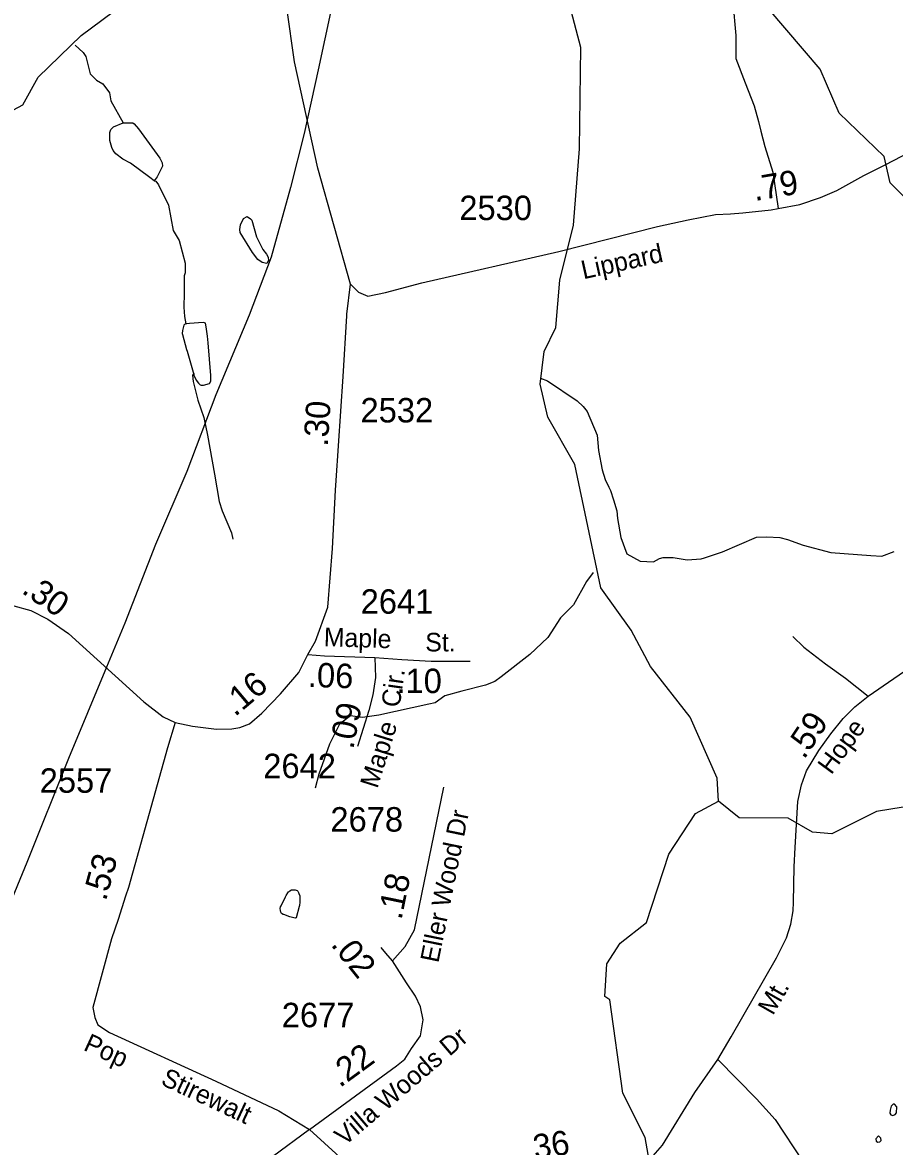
# Model space of a CAD drawing. Extents: x 1473865 to 1648260, y 639067 to 773536.
# Drawn here: x 1556744 to 1561206, y 667690 to 673439 of the extents above; entities that cross this region are included whole.
import ezdxf

# ---------------------------------------------------------------- set-up
doc = ezdxf.new("R2010")
doc.units = 0
for name, color, linetype in [('Exist Hydrographic Creek Single Shore', 7, 'Continuous'), ('Exist Hydrographic Misc Water Feature', 7, 'Continuous'), ('Exist Road Non-System Type 51', 7, 'Continuous'), ('Exist Road Secondary Mileage Hundredths English Label', 7, 'Continuous'), ('Exist Road Secondary Type 51 Attributed', 7, 'Continuous'), ('Exist Road Secondary Type 51 Label', 7, 'Continuous'), ('Exist Road Secondary Type 51 Number Label', 7, 'Continuous'), ('Exist Utilities Electrical Transmission Line', 7, 'Continuous')]:
    doc.layers.add(name, color=color, linetype=linetype)

msp = doc.modelspace()

# ---------------------------------------------------------------- linework, layer by layer
at = {"layer": 'Exist Hydrographic Creek Single Shore'}
for points in [[(1560304.5, 669456), (1560297.4, 669574.3), (1560160.4, 669885.6), (1559956.5, 670145.7), (1559858.5, 670331.6), (1559703.5, 670548.1), (1559570.5, 671177.7), (1559432.5, 671420.1), (1559393.4, 671588.3), (1559412.5, 671755.3), (1559472.5, 671878.8), (1559492.5, 672121.3), (1559563.5, 672402.2), (1559594.5, 672792.2), (1559601.4, 673310.7), (1559351.6, 674255.1), (1559302.9, 674358.3), (1559271.4, 674498.8)], [(1555070.4, 671875.8), (1555263.5, 671947.4), (1555572.5, 671960.9), (1555791.5, 672114), (1555983.4, 672146.2), (1556110.4, 672261.8), (1556286.5, 672333.7), (1556363.5, 672466.8), (1556399.4, 672646.6), (1556526.5, 672811.5), (1556578.5, 672928.5), (1556746.5, 673017.1), (1556823.5, 673159.9), (1557043.4, 673372.1), (1557481.5, 673698.1), (1557672.5, 673648.3), (1557798.5, 673678.6), (1557883.5, 673834.4), (1557865.7, 674112.6), (1557939.2, 674210.1), (1558074.5, 674332.8), (1558259.5, 674430.8)], [(1561675.9, 665105.2), (1561484.1, 665152.9), (1561127.3, 665283.8), (1560879.4, 665387.3), (1560665.3, 665624.6), (1560502.3, 665870.9), (1560370.4, 665978.5), (1560225.4, 666290), (1560086.4, 666516.1), (1560050.4, 666900.8), (1560011.4, 667052.6), (1559962.4, 667135.7), (1559931.4, 667326.6), (1559960.4, 667562.4), (1559929.4, 667737), (1559815.4, 667962.5), (1559748.5, 668439.9), (1559723.4, 668456.7), (1559733.4, 668623.9), (1559802.4, 668730.8), (1559937.4, 668836.5), (1560050.4, 669185.4), (1560186.5, 669392.7), (1560304.5, 669456)]]:
    msp.add_lwpolyline(points, dxfattribs=at)
at = {"layer": 'Exist Hydrographic Misc Water Feature'}
msp.add_line((1557617.4, 671650.6), (1557619.1, 671639.2), dxfattribs=at)
for points in [[(1561348.5, 672451.5), (1561183.5, 672618.9), (1561152.5, 672754.1), (1560922.5, 672975.5), (1560825.5, 673200.6), (1560563.4, 673504.6), (1560402.5, 673914.8), (1560221.5, 674102.4), (1560214.5, 674168.1), (1560140.5, 674268.1), (1559975.5, 674389.6), (1559861.5, 674549.4), (1559748.5, 674768.4), (1559732.5, 674840.9), (1559530.5, 675271.7), (1559472.5, 675322.1), (1559380.5, 675330.5)], [(1557013.2, 673322.3), (1557054.1, 673285.3), (1557067.8, 673265.1), (1557090.9, 673176.9), (1557122.6, 673144.5), (1557155.3, 673124.6), (1557189.8, 673079.7), (1557195.4, 673037.6), (1557259.3, 672925.3)], [(1557416.9, 672628.3), (1557395.1, 672645.3), (1557295.8, 672718.5), (1557258.1, 672738.9), (1557222.4, 672767.3), (1557208.6, 672783.5), (1557200.7, 672799.6), (1557191.2, 672835.7), (1557191.6, 672875.7), (1557195.8, 672891.6), (1557209.9, 672905.5), (1557259.3, 672925.3)], [(1557259.3, 672925.3), (1557308.1, 672926.3), (1557316.1, 672920.2), (1557337.9, 672894), (1557446.2, 672744.7), (1557457.9, 672720.6), (1557459.8, 672704.5), (1557433.1, 672648.9), (1557416.9, 672628.3)], [(1557416.9, 672628.3), (1557426.9, 672626.9), (1557440.7, 672608.8), (1557491.6, 672504.1), (1557515.7, 672374.2), (1557545.6, 672323.5), (1557576.3, 672207.1), (1557575.8, 672159.1), (1557571.6, 672143.2), (1557570.6, 672055.2), (1557569.9, 671983.2), (1557573.3, 671935.2), (1557580.4, 671897.3)], [(1557892.7, 672445.9), (1557911, 672435.2), (1557916.9, 672427.2), (1557942, 672342.9), (1557973.2, 672278.5), (1557993, 672254.3), (1558000.8, 672238.2), (1558002.6, 672222.2), (1557994.4, 672206.3), (1557970.6, 672210.6), (1557948.7, 672226.8), (1557921, 672263.2), (1557858.2, 672363.9), (1557856.3, 672379.9), (1557858.6, 672403.9), (1557875, 672435.7), (1557892.7, 672445.9)], [(1557580.4, 671897.3), (1557572.1, 671893.9), (1557568.9, 671889.9), (1557567.1, 671884.2), (1557565.4, 671877.6), (1557562.7, 671862.9), (1557561.7, 671848.1), (1557562.5, 671843.2), (1557583.6, 671765.9), (1557586, 671757.6), (1557617.4, 671650.6)], [(1557619.1, 671639.2), (1557632.5, 671608.6), (1557644.7, 671594.4), (1557652.8, 671585.3), (1557657.6, 671584.4), (1557661.7, 671584.4), (1557670.8, 671584.3), (1557700.4, 671592.1), (1557708, 671604.3), (1557706.8, 671633.8), (1557694, 671800.5), (1557690.4, 671835), (1557683.6, 671882.6), (1557680.5, 671900.7), (1557674.8, 671902.4), (1557668.2, 671904.2), (1557599.3, 671899.3), (1557585.4, 671897.9), (1557580.4, 671897.3)], [(1557619.1, 671639.2), (1557614, 671634.7), (1557617.7, 671602.6), (1557640.6, 671506.3), (1557671.6, 671418), (1557691.3, 671328.4), (1557726.4, 671129.3), (1557750.9, 670989), (1557766.3, 670940.8), (1557813.2, 670828.2), (1557820.8, 670796.2)], [(1557617.4, 671650.6), (1557622.3, 671640.7), (1557619.1, 671639.2)], [(1559393.5, 671620), (1559430.3, 671605.5), (1559581.3, 671503.7), (1559613, 671475.3), (1559632.7, 671449.1), (1559683.9, 671327.4), (1559690.5, 671250.4), (1559709.4, 671150.2), (1559724.9, 671102), (1559744.5, 671061.8), (1559752.3, 671045.7), (1559767.7, 670997.5), (1559785.2, 670941.3), (1559788.8, 670901.2), (1559805.7, 670805), (1559836.7, 670720.6), (1559904.3, 670683.9), (1559972.4, 670681.1), (1560002.5, 670696.8), (1560022.6, 670702.5), (1560072.6, 670701.9), (1560144.5, 670691.1), (1560216.6, 670696.2), (1560232.7, 670700), (1560325.1, 670731), (1560500, 670807), (1560552, 670808.4), (1560618, 670805.6), (1560657.9, 670795.1), (1560737.5, 670766.2), (1560879.2, 670728.5), (1561085.1, 670712.1), (1561141.1, 670709.5), (1561203.4, 670732.7)], [(1559664.1, 670626.5), (1559629.1, 670579.1), (1559563.7, 670459.8), (1559497, 670394.6), (1559431.9, 670293.7), (1559338.9, 670206.4), (1559193.5, 670092.1), (1559161.3, 670068.5), (1559113, 670049.1), (1558992.6, 670018.4), (1558904.4, 669995.5), (1558856, 669960), (1558823.8, 669952.4), (1558567.1, 669895.4), (1558483, 669884.3), (1558423, 669893.1), (1558366.5, 669849.7), (1558315.4, 669748.3), (1558259.7, 669594.9), (1558240.8, 669523.1)], [(1563318.4, 667461.8), (1563195.4, 667638.2), (1563174.5, 667871.7), (1563126.4, 667997.4), (1562839.4, 668328.2), (1562832.4, 668426.8), (1562750.4, 668546.6), (1562822.4, 668896.4), (1562789.5, 668929.9), (1562580.4, 668898), (1562406.4, 668944.2), (1562182.4, 669070.1), (1562092.4, 669180.3), (1562028.4, 669349), (1561806.5, 669527.5), (1561673.5, 669579.4), (1561514.5, 669562.9), (1561312.4, 669435.6), (1561112.5, 669403.5), (1560885.5, 669290), (1560785.4, 669298.6), (1560661.5, 669370), (1560411.4, 669371.8), (1560304.5, 669456)], [(1558143.5, 668859), (1558138.7, 668857.9), (1558112, 668865.4), (1558081.5, 668875.9), (1558078.3, 668877.3), (1558069.8, 668881.5), (1558066.9, 668885.2), (1558065, 668888.7), (1558063.6, 668897.1), (1558062.9, 668907.7), (1558064.8, 668915.1), (1558066.8, 668920.3), (1558089, 668967.4), (1558093.1, 668974.5), (1558101.6, 668988.1), (1558105.4, 668992.1), (1558108.2, 668994.6), (1558112.2, 668997.7), (1558119.8, 669002), (1558126.4, 669002.7), (1558139.3, 669002.3), (1558144.4, 669001.3), (1558149.9, 668999.2), (1558152.7, 668996.1), (1558155.8, 668990), (1558158.6, 668983.7), (1558163.1, 668972.9), (1558163.7, 668958.9), (1558163.6, 668949.4), (1558163.2, 668940), (1558160.7, 668922.2), (1558159.8, 668917.9), (1558143.5, 668859)], [(1561183.5, 667876.4), (1561181.6, 667860.7), (1561187.5, 667852.7), (1561197.5, 667848.5), (1561209.6, 667854.4), (1561215.6, 667862.3), (1561218, 667892.3), (1561206.1, 667906.5), (1561198.1, 667906.6), (1561187.9, 667896.7), (1561183.5, 667876.4)], [(1561122.8, 667745.3), (1561110.1, 667729.6), (1561112, 667717.6), (1561119.8, 667711.5), (1561129.9, 667713.4), (1561138, 667721.2), (1561136.1, 667733.2), (1561122.8, 667745.3)]]:
    msp.add_lwpolyline(points, dxfattribs=at)
at = {"layer": 'Exist Road Non-System Type 51'}
for points in [[(1560378.4, 673541.8), (1560393, 673371.8), (1560394.1, 673254), (1560441.1, 673130.2), (1560488, 673013), (1560509.1, 672931.7)], [(1560509.1, 672931.7), (1560521.9, 672882.5), (1560542.2, 672804.2), (1560582.7, 672673.8), (1560610.8, 672487.9)], [(1560684.7, 670297.7), (1560742.2, 670243.1), (1560851.6, 670158.1), (1560954.9, 670085.2), (1561070.3, 669992.8)]]:
    msp.add_lwpolyline(points, dxfattribs=at)
at = {"layer": 'Exist Road Secondary Type 51 Attributed'}
for points in [[(1558421.7, 672101.1), (1558254.7, 672692.9), (1558135.5, 673238), (1558056.4, 673791), (1558049.7, 673925), (1558010.9, 674035.3), (1557970.5, 674132.9), (1557939.2, 674210.1), (1557902.5, 674316.9), (1557879.9, 674400.7), (1557859.9, 674633), (1557849.3, 674791.1), (1557837, 674971.2), (1557827.1, 675213.4), (1557809, 675437.6), (1557797.3, 675679.8), (1557760, 676212.4), (1557744, 676668.5), (1557744.5, 677160.4), (1557747.3, 677276.8), (1557748.8, 677432.8), (1557735.9, 677902.4)], [(1558421.7, 672101.1), (1558463.2, 672058.8), (1558511, 672038.2), (1558601.3, 672057.4), (1558787.8, 672107.7), (1559487.5, 672267.2), (1559992.9, 672394.7), (1560149.3, 672429.1), (1560289.7, 672455.9), (1560366, 672460.7), (1560429.7, 672464.7), (1560574, 672481.2), (1560610.8, 672487.9), (1560720.4, 672507.9), (1560826.7, 672542.9), (1560911.1, 672580.2), (1561047.9, 672656.9), (1561158.4, 672709.9), (1561413.7, 672843.6)], [(1558204.7, 670206.7), (1558243.3, 670274.4), (1558306.8, 670447.8), (1558329.5, 670747.7), (1558346.2, 671047.5), (1558349.5, 671096.8), (1558385.3, 671627.4), (1558403.6, 671937.9), (1558404.2, 671947.3), (1558421.7, 672101.1)], [(1556144.6, 670572.3), (1556436.5, 670513.2), (1556700, 670454.6), (1556786, 670431.9), (1556873.5, 670387.1), (1556978.9, 670314.1), (1557364, 669964.4), (1557463.3, 669887.3), (1557525.2, 669858.9)], [(1560301.6, 668135.2), (1560370.6, 668250.7), (1560602.3, 668654.6), (1560653.2, 668758.2), (1560675.8, 668828), (1560686.4, 668896), (1560688.9, 668940), (1560692.3, 669120), (1560697.3, 669219.9), (1560711.3, 669454), (1560730, 669539.8), (1560754.7, 669611.6), (1560817.6, 669714.9), (1560880.5, 669800.5), (1560943.2, 669879.9), (1561001.8, 669939.3), (1561070.3, 669992.8), (1561333.9, 670174.3), (1561466.7, 670259.1), (1561822.9, 670488), (1561923.6, 670559)], [(1557525.2, 669858.9), (1557613, 669840.1), (1557737, 669824.8), (1557815, 669826.2), (1557855.2, 669833.8), (1557905.4, 669851.4), (1557967.7, 669906.8), (1558064.8, 670005.9), (1558157.8, 670115), (1558204.7, 670206.7)], [(1558204.7, 670206.7), (1558288.6, 670199.8), (1558546.6, 670191.4)], [(1558546.6, 670191.4), (1558549.7, 670089.3), (1558536.9, 669999.5), (1558516.3, 669919.7), (1558458.7, 669736.1)], [(1558546.6, 670191.4), (1558684.6, 670180.2), (1558834.7, 670172.8), (1559034.8, 670173)], [(1557525.2, 669858.9), (1557485.9, 669729.2), (1557285.6, 669014.9), (1557271.8, 668970.9), (1557234.1, 668851.3), (1557199.3, 668751.5), (1557103.9, 668400.3), (1557113.5, 668350.3), (1557129.1, 668312.1), (1557189, 668273.5), (1557733, 668024.4), (1558055.7, 667873.4), (1558212.3, 667777.2)], [(1558636.6, 668639.8), (1558701.4, 668712.9), (1558750.4, 668798), (1558899.1, 669527.8)], [(1558636.6, 668639.8), (1558603.4, 668678.3), (1558578.9, 668707.1)], [(1558212.3, 667777.2), (1558657.6, 668102.6), (1558700, 668136.5), (1558733.9, 668191.7), (1558780.5, 668255.3), (1558793.6, 668337.8), (1558780.5, 668403.8), (1558755.1, 668458.9), (1558708.4, 668526.8), (1558636.6, 668639.8)], [(1558741.6, 667295.5), (1558798.1, 667349), (1558880.5, 667398.1), (1559069.3, 667492.4), (1559199.7, 667531.4), (1559350.1, 667553.9), (1559476.2, 667556.8), (1559598.2, 667553.5), (1559716.3, 667558.5), (1559836.4, 667577.3), (1559926.8, 667608.5), (1559971.1, 667642.2), (1560017.7, 667697.7), (1560184, 667966.3), (1560301.6, 668135.2)], [(1560301.6, 668135.2), (1560499.9, 667933.3), (1560595, 667828.5), (1560737.1, 667613.2)], [(1558212.3, 667777.2), (1557834.2, 667497.3), (1557222.2, 667066.9), (1556746.9, 666725.3), (1556605.9, 666628.5), (1556501.2, 666546.3), (1556223, 666551)], [(1558212.3, 667777.2), (1558423.4, 667583.9), (1558538.5, 667486.9), (1558741.6, 667295.5)]]:
    msp.add_lwpolyline(points, dxfattribs=at)
at = {"layer": 'Exist Utilities Electrical Transmission Line'}
msp.add_lwpolyline([(1558364.7, 673697.6), (1558257.3, 673196.7), (1558185.9, 672871.4), (1558114.9, 672594.1), (1558017.1, 672239.1), (1557903.8, 671942.2), (1557733.5, 671534.1), (1557585.3, 671141.7), (1557425.3, 670769.3), (1557266.9, 670367.1), (1557174.5, 670142.1), (1556979.4, 669674), (1556765.7, 669142.3), (1556554.2, 668632.7), (1556445.4, 668367.8), (1556306.9, 668139.2), (1556068.2, 667717.9), (1555803.4, 667254.6)], dxfattribs=at)

# ---------------------------------------------------------------- texts
at = {"layer": 'Exist Road Secondary Mileage Hundredths English Label'}
for s, rotation, p in [('.79', 9.60562, (1560491.2, 672525.3)), ('.30', 86.13958, (1558305.6, 671268)), ('.30', 325.30189, (1556734.5, 670524.4)), ('.06', 358.13217, (1558202.5, 670040.7)), ('.10', 0.04603, (1558657.4, 670008.8)), ('.16', 40.08103, (1557831, 669885.2)), ('.09', 78.79339, (1558436.1, 669718.4)), ('.59', 56.38558, (1560743.1, 669666)), ('.53', 74.81362, (1557170.6, 668942.1)), ('.18', 78.48145, (1558682.9, 668845.6)), ('.02', 308.68812, (1558318, 668721.4)), ('.22', 36.16107, (1558367.6, 667988)), ('.36', 8.54196, (1559320.1, 667617.4))]:
    msp.add_text(s, height=125, rotation=rotation, dxfattribs=at).set_placement(p)
at = {"layer": 'Exist Road Secondary Type 51 Label'}
for s, rotation, p in [('Lippard', 12.42872, (1559613.8, 672125.1)), ('Maple', 358.13217, (1558284.5, 670249.2)), ('St.', 0.04603, (1558804.7, 670222)), ('Cir.', 81.87312, (1558673.2, 669932.2)), ('Maple', 72.58576, (1558559.5, 669517.3)), ('Hope', 53.65741, (1560881.8, 669587.6)), ('Eller Wood Dr', 78.48143, (1558871.3, 668625.8)), ('Mt.', 60.16359, (1560583.3, 668356.5)), ('Villa Woods Dr', 40.48161, (1558391.5, 667690)), ('Pop', 335.39768, (1557050.8, 668184.9)), ('Stirewalt', 334.92615, (1557446, 668009.3))]:
    msp.add_text(s, height=95, rotation=rotation, dxfattribs=at).set_placement(p)
at = {"layer": 'Exist Road Secondary Type 51 Number Label'}
for s, p in [('2530', (1558978.9, 672428)), ('2532', (1558473.3, 671393.2)), ('2641', (1558474.1, 670415)), ('2642', (1557975.8, 669573.9)), ('2557', (1556831.9, 669499.2)), ('2678', (1558319.3, 669300.7)), ('2677', (1558070.5, 668300.1))]:
    msp.add_text(s, height=125, dxfattribs=at).set_placement(p)

doc.saveas('drawing.dxf')
